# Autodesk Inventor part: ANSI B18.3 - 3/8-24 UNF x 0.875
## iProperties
Created: 2006-02
Part Number: ANSI B18.3 - 3/8-24 UNF x 0.875
Material: Steel, Mild
Description: Hexagon Socket Flat Countersunk Head Cap Screw
Document SubType Name: Modeling
Standard: ANSI B18.3
Designer: rollin42
Standards Organization: ANSI
Language: en-US
Size Designation: 3/8-24 UNF x 0.875
Categories: <MemberInstance><Categories><Category DisplayName="Fasteners" InternalName="e4da775c-781d-43d5-af7c-5136215cf5a6" Mnemonic="FSTN"><Category DisplayName="Bolts"
Density: 1 g/cm^3
Author: rollin42
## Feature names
1. Body [Revolution]
2. Slot [Extrusion]
3. Chamfer1
